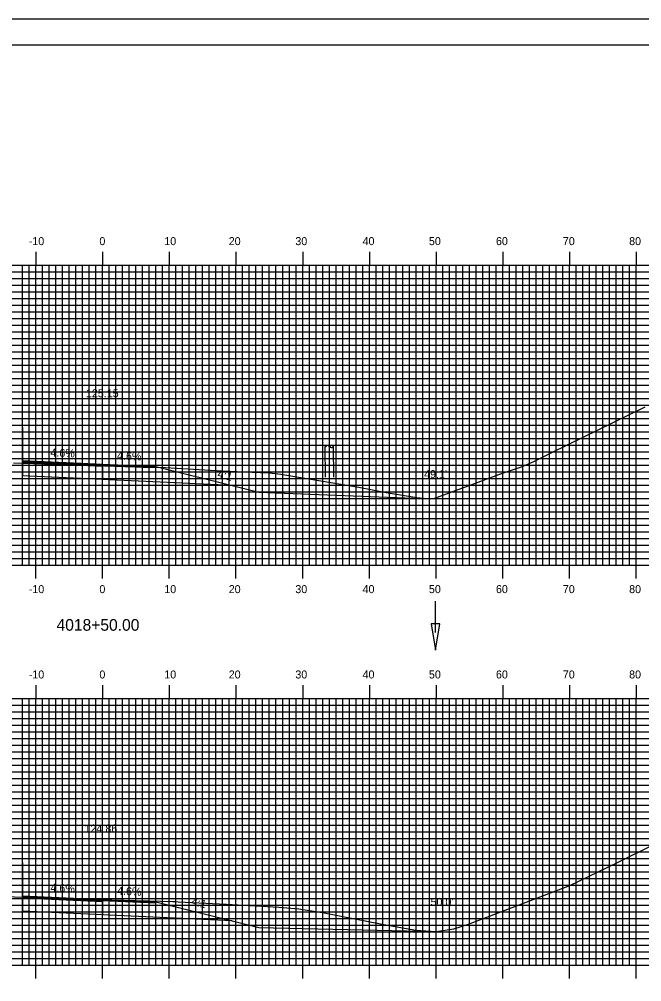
# Model space of a CAD drawing. Extents: x 854508 to 854851, y 364661 to 364881.
# Drawn here: x 854661.3 to 854754.7, y 364736.9 to 364881.3 of the extents above; entities that cross this region are included whole.
import ezdxf

# ---------------------------------------------------------------- set-up
doc = ezdxf.new("R2010")
doc.units = 0
for name, color, linetype in [('ANNOTATION', 7, 'Continuous'), ('BORDER', 7, 'Continuous'), ('D_Drainage_Ditch_Line', 7, 'Continuous'), ('D_Roadway_Centerline_Text', 7, 'Continuous'), ('D_Roadway_Edge_Shoulder', 7, 'Continuous'), ('D_Roadway_Edge_TW', 7, 'Continuous'), ('D_Roadway_Pavement', 7, 'Continuous'), ('D_Roadway_SubGrade', 7, 'Continuous'), ('D_Text_Standard', 7, 'Continuous'), ('H_V ANNOTATION', 7, 'Continuous'), ('M_Roadway_Centerline', 7, 'Continuous'), ('MAJOR', 7, 'Continuous'), ('MINOR', 7, 'Continuous'), ('PLOT BOUNDARY', 7, 'Continuous'), ('S_Roadway_Centerline', 7, 'Continuous'), ('S_Utilities_Pole_StreetLight', 7, 'Continuous')]:
    doc.layers.add(name, color=color, linetype=linetype)

msp = doc.modelspace()

# ---------------------------------------------------------------- linework, layer by layer
at = {"layer": 'ANNOTATION'}
for points in [[(854693.26, 364811.3), (854697.26, 364810.3), (854722.98, 364809.33)], [(854693.25, 364746.01), (854697.25, 364745.01), (854723.85, 364744.4)]]:
    msp.add_lwpolyline(points, dxfattribs=at)
at = {"layer": 'BORDER'}
msp.add_lwpolyline([(854524.23, 364667.37), (854844.23, 364667.37), (854844.23, 364877.37), (854524.23, 364877.37)], close=True, dxfattribs=at)
at = {"layer": 'D_Drainage_Ditch_Line'}
msp.add_line((854723.75, 364789.25), (854723.75, 364793.95), dxfattribs=at)
msp.add_lwpolyline([(854724.4, 364790.56), (854723.09, 364790.56), (854723.75, 364786.63)], close=True, dxfattribs=at)
at = {"layer": 'D_Roadway_Edge_Shoulder'}
for points in [[(854673.83, 364814.52), (854681.83, 364814.15), (854681.83, 364813.99), (854673.83, 364814.36)], [(854673.83, 364749.23), (854681.83, 364748.86), (854681.83, 364748.7), (854673.83, 364749.07)]]:
    msp.add_lwpolyline(points, close=True, dxfattribs=at)
at = {"layer": 'D_Roadway_Edge_TW'}
for points in [[(854661.83, 364815.07), (854673.83, 364814.52), (854673.83, 364814.36), (854661.83, 364814.91)], [(854661.83, 364749.78), (854673.83, 364749.23), (854673.83, 364749.07), (854661.83, 364749.61)]]:
    msp.add_lwpolyline(points, close=True, dxfattribs=at)
at = {"layer": 'D_Roadway_Pavement'}
for points in [[(854661.83, 364814.91), (854673.83, 364814.36), (854673.83, 364814.19), (854661.83, 364814.74)], [(854661.83, 364749.61), (854673.83, 364749.07), (854673.83, 364748.9), (854661.83, 364749.45)]]:
    msp.add_lwpolyline(points, close=True, dxfattribs=at)
for points in [[(854661.83, 364814.91), (854661.83, 364814.74)], [(854673.83, 364814.36), (854673.83, 364814.19)], [(854673.83, 364814.36), (854673.83, 364814.19)], [(854661.83, 364749.61), (854661.83, 364749.45)], [(854673.83, 364749.07), (854673.83, 364748.9)], [(854673.83, 364749.07), (854673.83, 364748.9)]]:
    msp.add_lwpolyline(points, dxfattribs=at)
at = {"layer": 'D_Roadway_SubGrade'}
for p, q in [((854661.83, 364820.03), (854661.83, 364812.74)), ((854661.83, 364754.74), (854661.83, 364747.45))]:
    msp.add_line(p, q, dxfattribs=at)
for points in [[(854661.83, 364814.74), (854673.83, 364814.19), (854673.83, 364812.19), (854661.83, 364812.74)], [(854673.83, 364814.19), (854673.83, 364814.36), (854681.83, 364813.99), (854681.83, 364814.15), (854693.26, 364811.3), (854673.83, 364812.19)], [(854661.83, 364749.45), (854673.83, 364748.9), (854673.83, 364746.9), (854661.83, 364747.45)], [(854673.83, 364748.9), (854673.83, 364749.07), (854681.83, 364748.7), (854681.83, 364748.86), (854693.25, 364746.01), (854673.83, 364746.9)]]:
    msp.add_lwpolyline(points, close=True, dxfattribs=at)
at = {"layer": 'MAJOR'}
for p, q in [((854663.83, 364846.37), (854663.83, 364844.37)), ((854673.83, 364846.37), (854673.83, 364844.37)), ((854683.83, 364846.37), (854683.83, 364844.37)), ((854693.83, 364846.37), (854693.83, 364844.37)), ((854703.83, 364846.37), (854703.83, 364844.37)), ((854713.83, 364846.37), (854713.83, 364844.37)), ((854723.83, 364846.37), (854723.83, 364844.37)), ((854733.83, 364846.37), (854733.83, 364844.37)), ((854743.83, 364846.37), (854743.83, 364844.37)), ((854753.83, 364846.37), (854753.83, 364844.37)), ((854533.83, 364844.37), (854813.83, 364844.37)), ((854533.83, 364844.37), (854813.83, 364844.37)), ((854663.83, 364799.37), (854663.83, 364844.37)), ((854673.83, 364799.37), (854673.83, 364844.37)), ((854683.83, 364799.37), (854683.83, 364844.37)), ((854693.83, 364799.37), (854693.83, 364844.37)), ((854703.83, 364799.37), (854703.83, 364844.37)), ((854713.83, 364799.37), (854713.83, 364844.37)), ((854723.83, 364799.37), (854723.83, 364844.37)), ((854733.83, 364799.37), (854733.83, 364844.37)), ((854743.83, 364799.37), (854743.83, 364844.37)), ((854753.83, 364799.37), (854753.83, 364844.37)), ((854533.83, 364839.37), (854813.83, 364839.37)), ((854533.83, 364834.37), (854813.83, 364834.37)), ((854533.83, 364829.37), (854813.83, 364829.37)), ((854533.83, 364824.37), (854813.83, 364824.37)), ((854533.83, 364819.37), (854813.83, 364819.37)), ((854533.83, 364814.37), (854813.83, 364814.37)), ((854533.83, 364809.37), (854813.83, 364809.37)), ((854533.83, 364804.37), (854813.83, 364804.37)), ((854533.83, 364799.37), (854813.83, 364799.37)), ((854533.83, 364799.37), (854813.83, 364799.37)), ((854663.83, 364797.37), (854663.83, 364799.37)), ((854673.83, 364797.37), (854673.83, 364799.37)), ((854683.83, 364797.37), (854683.83, 364799.37)), ((854693.83, 364797.37), (854693.83, 364799.37)), ((854703.83, 364797.37), (854703.83, 364799.37)), ((854713.83, 364797.37), (854713.83, 364799.37)), ((854723.83, 364797.37), (854723.83, 364799.37)), ((854733.83, 364797.37), (854733.83, 364799.37)), ((854743.83, 364797.37), (854743.83, 364799.37)), ((854753.83, 364797.37), (854753.83, 364799.37)), ((854663.83, 364781.37), (854663.83, 364779.37)), ((854673.83, 364781.37), (854673.83, 364779.37)), ((854683.83, 364781.37), (854683.83, 364779.37)), ((854693.83, 364781.37), (854693.83, 364779.37)), ((854703.83, 364781.37), (854703.83, 364779.37)), ((854713.83, 364781.37), (854713.83, 364779.37)), ((854723.83, 364781.37), (854723.83, 364779.37)), ((854733.83, 364781.37), (854733.83, 364779.37)), ((854743.83, 364781.37), (854743.83, 364779.37)), ((854753.83, 364781.37), (854753.83, 364779.37)), ((854533.83, 364779.37), (854813.83, 364779.37)), ((854533.83, 364779.37), (854813.83, 364779.37)), ((854663.83, 364739.37), (854663.83, 364779.37)), ((854673.83, 364739.37), (854673.83, 364779.37)), ((854683.83, 364739.37), (854683.83, 364779.37)), ((854693.83, 364739.37), (854693.83, 364779.37)), ((854703.83, 364739.37), (854703.83, 364779.37)), ((854713.83, 364739.37), (854713.83, 364779.37)), ((854723.83, 364739.37), (854723.83, 364779.37)), ((854733.83, 364739.37), (854733.83, 364779.37)), ((854743.83, 364739.37), (854743.83, 364779.37)), ((854753.83, 364739.37), (854753.83, 364779.37)), ((854533.83, 364774.37), (854813.83, 364774.37)), ((854533.83, 364769.37), (854813.83, 364769.37)), ((854533.83, 364764.37), (854813.83, 364764.37)), ((854533.83, 364759.37), (854813.83, 364759.37)), ((854533.83, 364754.37), (854813.83, 364754.37)), ((854533.83, 364749.37), (854813.83, 364749.37)), ((854533.83, 364744.37), (854813.83, 364744.37)), ((854533.83, 364739.37), (854813.83, 364739.37)), ((854533.83, 364739.37), (854813.83, 364739.37)), ((854663.83, 364737.37), (854663.83, 364739.37)), ((854673.83, 364737.37), (854673.83, 364739.37)), ((854683.83, 364737.37), (854683.83, 364739.37)), ((854693.83, 364737.37), (854693.83, 364739.37)), ((854703.83, 364737.37), (854703.83, 364739.37)), ((854713.83, 364737.37), (854713.83, 364739.37)), ((854723.83, 364737.37), (854723.83, 364739.37)), ((854733.83, 364737.37), (854733.83, 364739.37)), ((854743.83, 364737.37), (854743.83, 364739.37)), ((854753.83, 364737.37), (854753.83, 364739.37))]:
    msp.add_line(p, q, dxfattribs=at)
at = {"layer": 'MINOR'}
for p, q in [((854661.83, 364799.37), (854661.83, 364844.37)), ((854662.83, 364799.37), (854662.83, 364844.37)), ((854664.83, 364799.37), (854664.83, 364844.37)), ((854665.83, 364799.37), (854665.83, 364844.37)), ((854666.83, 364799.37), (854666.83, 364844.37)), ((854667.83, 364799.37), (854667.83, 364844.37)), ((854668.83, 364799.37), (854668.83, 364844.37)), ((854669.83, 364799.37), (854669.83, 364844.37)), ((854670.83, 364799.37), (854670.83, 364844.37)), ((854671.83, 364799.37), (854671.83, 364844.37)), ((854672.83, 364799.37), (854672.83, 364844.37)), ((854674.83, 364799.37), (854674.83, 364844.37)), ((854675.83, 364799.37), (854675.83, 364844.37)), ((854676.83, 364799.37), (854676.83, 364844.37)), ((854677.83, 364799.37), (854677.83, 364844.37)), ((854678.83, 364799.37), (854678.83, 364844.37)), ((854679.83, 364799.37), (854679.83, 364844.37)), ((854680.83, 364799.37), (854680.83, 364844.37)), ((854681.83, 364799.37), (854681.83, 364844.37)), ((854682.83, 364799.37), (854682.83, 364844.37)), ((854684.83, 364799.37), (854684.83, 364844.37)), ((854685.83, 364799.37), (854685.83, 364844.37)), ((854686.83, 364799.37), (854686.83, 364844.37)), ((854687.83, 364799.37), (854687.83, 364844.37)), ((854688.83, 364799.37), (854688.83, 364844.37)), ((854689.83, 364799.37), (854689.83, 364844.37)), ((854690.83, 364799.37), (854690.83, 364844.37)), ((854691.83, 364799.37), (854691.83, 364844.37)), ((854692.83, 364799.37), (854692.83, 364844.37)), ((854694.83, 364799.37), (854694.83, 364844.37)), ((854695.83, 364799.37), (854695.83, 364844.37)), ((854696.83, 364799.37), (854696.83, 364844.37)), ((854697.83, 364799.37), (854697.83, 364844.37)), ((854698.83, 364799.37), (854698.83, 364844.37)), ((854699.83, 364799.37), (854699.83, 364844.37)), ((854700.83, 364799.37), (854700.83, 364844.37)), ((854701.83, 364799.37), (854701.83, 364844.37)), ((854702.83, 364799.37), (854702.83, 364844.37)), ((854704.83, 364799.37), (854704.83, 364844.37)), ((854705.83, 364799.37), (854705.83, 364844.37)), ((854706.83, 364799.37), (854706.83, 364844.37)), ((854707.83, 364799.37), (854707.83, 364844.37)), ((854708.83, 364799.37), (854708.83, 364844.37)), ((854709.83, 364799.37), (854709.83, 364844.37)), ((854710.83, 364799.37), (854710.83, 364844.37)), ((854711.83, 364799.37), (854711.83, 364844.37)), ((854712.83, 364799.37), (854712.83, 364844.37)), ((854714.83, 364799.37), (854714.83, 364844.37)), ((854715.83, 364799.37), (854715.83, 364844.37)), ((854716.83, 364799.37), (854716.83, 364844.37)), ((854717.83, 364799.37), (854717.83, 364844.37)), ((854718.83, 364799.37), (854718.83, 364844.37)), ((854719.83, 364799.37), (854719.83, 364844.37)), ((854720.83, 364799.37), (854720.83, 364844.37)), ((854721.83, 364799.37), (854721.83, 364844.37)), ((854722.83, 364799.37), (854722.83, 364844.37)), ((854724.83, 364799.37), (854724.83, 364844.37)), ((854725.83, 364799.37), (854725.83, 364844.37)), ((854726.83, 364799.37), (854726.83, 364844.37)), ((854727.83, 364799.37), (854727.83, 364844.37)), ((854728.83, 364799.37), (854728.83, 364844.37)), ((854729.83, 364799.37), (854729.83, 364844.37)), ((854730.83, 364799.37), (854730.83, 364844.37)), ((854731.83, 364799.37), (854731.83, 364844.37)), ((854732.83, 364799.37), (854732.83, 364844.37)), ((854734.83, 364799.37), (854734.83, 364844.37)), ((854735.83, 364799.37), (854735.83, 364844.37)), ((854736.83, 364799.37), (854736.83, 364844.37)), ((854737.83, 364799.37), (854737.83, 364844.37)), ((854738.83, 364799.37), (854738.83, 364844.37)), ((854739.83, 364799.37), (854739.83, 364844.37)), ((854740.83, 364799.37), (854740.83, 364844.37)), ((854741.83, 364799.37), (854741.83, 364844.37)), ((854742.83, 364799.37), (854742.83, 364844.37)), ((854744.83, 364799.37), (854744.83, 364844.37)), ((854745.83, 364799.37), (854745.83, 364844.37)), ((854746.83, 364799.37), (854746.83, 364844.37)), ((854747.83, 364799.37), (854747.83, 364844.37)), ((854748.83, 364799.37), (854748.83, 364844.37)), ((854749.83, 364799.37), (854749.83, 364844.37)), ((854750.83, 364799.37), (854750.83, 364844.37)), ((854751.83, 364799.37), (854751.83, 364844.37)), ((854752.83, 364799.37), (854752.83, 364844.37)), ((854533.83, 364843.37), (854813.83, 364843.37)), ((854533.83, 364842.37), (854813.83, 364842.37)), ((854533.83, 364841.37), (854813.83, 364841.37)), ((854533.83, 364840.37), (854813.83, 364840.37)), ((854533.83, 364838.37), (854813.83, 364838.37)), ((854533.83, 364837.37), (854813.83, 364837.37)), ((854533.83, 364836.37), (854813.83, 364836.37)), ((854533.83, 364835.37), (854813.83, 364835.37)), ((854533.83, 364833.37), (854813.83, 364833.37)), ((854533.83, 364832.37), (854813.83, 364832.37)), ((854533.83, 364831.37), (854813.83, 364831.37)), ((854533.83, 364830.37), (854813.83, 364830.37)), ((854533.83, 364828.37), (854813.83, 364828.37)), ((854533.83, 364827.37), (854813.83, 364827.37)), ((854533.83, 364826.37), (854813.83, 364826.37)), ((854533.83, 364825.37), (854813.83, 364825.37)), ((854533.83, 364823.37), (854813.83, 364823.37)), ((854533.83, 364822.37), (854813.83, 364822.37)), ((854533.83, 364821.37), (854813.83, 364821.37)), ((854533.83, 364820.37), (854813.83, 364820.37)), ((854533.83, 364818.37), (854813.83, 364818.37)), ((854533.83, 364817.37), (854813.83, 364817.37)), ((854533.83, 364816.37), (854813.83, 364816.37)), ((854533.83, 364815.37), (854813.83, 364815.37)), ((854533.83, 364813.37), (854813.83, 364813.37)), ((854533.83, 364812.37), (854813.83, 364812.37)), ((854533.83, 364811.37), (854813.83, 364811.37)), ((854533.83, 364810.37), (854813.83, 364810.37)), ((854533.83, 364808.37), (854813.83, 364808.37)), ((854533.83, 364807.37), (854813.83, 364807.37)), ((854533.83, 364806.37), (854813.83, 364806.37)), ((854533.83, 364805.37), (854813.83, 364805.37)), ((854533.83, 364803.37), (854813.83, 364803.37)), ((854533.83, 364802.37), (854813.83, 364802.37)), ((854533.83, 364801.37), (854813.83, 364801.37)), ((854533.83, 364800.37), (854813.83, 364800.37)), ((854661.83, 364739.37), (854661.83, 364779.37)), ((854662.83, 364739.37), (854662.83, 364779.37)), ((854664.83, 364739.37), (854664.83, 364779.37)), ((854665.83, 364739.37), (854665.83, 364779.37)), ((854666.83, 364739.37), (854666.83, 364779.37)), ((854667.83, 364739.37), (854667.83, 364779.37)), ((854668.83, 364739.37), (854668.83, 364779.37)), ((854669.83, 364739.37), (854669.83, 364779.37)), ((854670.83, 364739.37), (854670.83, 364779.37)), ((854671.83, 364739.37), (854671.83, 364779.37)), ((854672.83, 364739.37), (854672.83, 364779.37)), ((854674.83, 364739.37), (854674.83, 364779.37)), ((854675.83, 364739.37), (854675.83, 364779.37)), ((854676.83, 364739.37), (854676.83, 364779.37)), ((854677.83, 364739.37), (854677.83, 364779.37)), ((854678.83, 364739.37), (854678.83, 364779.37)), ((854679.83, 364739.37), (854679.83, 364779.37)), ((854680.83, 364739.37), (854680.83, 364779.37)), ((854681.83, 364739.37), (854681.83, 364779.37)), ((854682.83, 364739.37), (854682.83, 364779.37)), ((854684.83, 364739.37), (854684.83, 364779.37)), ((854685.83, 364739.37), (854685.83, 364779.37)), ((854686.83, 364739.37), (854686.83, 364779.37)), ((854687.83, 364739.37), (854687.83, 364779.37)), ((854688.83, 364739.37), (854688.83, 364779.37)), ((854689.83, 364739.37), (854689.83, 364779.37)), ((854690.83, 364739.37), (854690.83, 364779.37)), ((854691.83, 364739.37), (854691.83, 364779.37)), ((854692.83, 364739.37), (854692.83, 364779.37)), ((854694.83, 364739.37), (854694.83, 364779.37)), ((854695.83, 364739.37), (854695.83, 364779.37)), ((854696.83, 364739.37), (854696.83, 364779.37)), ((854697.83, 364739.37), (854697.83, 364779.37)), ((854698.83, 364739.37), (854698.83, 364779.37)), ((854699.83, 364739.37), (854699.83, 364779.37)), ((854700.83, 364739.37), (854700.83, 364779.37)), ((854701.83, 364739.37), (854701.83, 364779.37)), ((854702.83, 364739.37), (854702.83, 364779.37)), ((854704.83, 364739.37), (854704.83, 364779.37)), ((854705.83, 364739.37), (854705.83, 364779.37)), ((854706.83, 364739.37), (854706.83, 364779.37)), ((854707.83, 364739.37), (854707.83, 364779.37)), ((854708.83, 364739.37), (854708.83, 364779.37)), ((854709.83, 364739.37), (854709.83, 364779.37)), ((854710.83, 364739.37), (854710.83, 364779.37)), ((854711.83, 364739.37), (854711.83, 364779.37)), ((854712.83, 364739.37), (854712.83, 364779.37)), ((854714.83, 364739.37), (854714.83, 364779.37)), ((854715.83, 364739.37), (854715.83, 364779.37)), ((854716.83, 364739.37), (854716.83, 364779.37)), ((854717.83, 364739.37), (854717.83, 364779.37)), ((854718.83, 364739.37), (854718.83, 364779.37)), ((854719.83, 364739.37), (854719.83, 364779.37)), ((854720.83, 364739.37), (854720.83, 364779.37)), ((854721.83, 364739.37), (854721.83, 364779.37)), ((854722.83, 364739.37), (854722.83, 364779.37)), ((854724.83, 364739.37), (854724.83, 364779.37)), ((854725.83, 364739.37), (854725.83, 364779.37)), ((854726.83, 364739.37), (854726.83, 364779.37)), ((854727.83, 364739.37), (854727.83, 364779.37)), ((854728.83, 364739.37), (854728.83, 364779.37)), ((854729.83, 364739.37), (854729.83, 364779.37)), ((854730.83, 364739.37), (854730.83, 364779.37)), ((854731.83, 364739.37), (854731.83, 364779.37)), ((854732.83, 364739.37), (854732.83, 364779.37)), ((854734.83, 364739.37), (854734.83, 364779.37)), ((854735.83, 364739.37), (854735.83, 364779.37)), ((854736.83, 364739.37), (854736.83, 364779.37)), ((854737.83, 364739.37), (854737.83, 364779.37)), ((854738.83, 364739.37), (854738.83, 364779.37)), ((854739.83, 364739.37), (854739.83, 364779.37)), ((854740.83, 364739.37), (854740.83, 364779.37)), ((854741.83, 364739.37), (854741.83, 364779.37)), ((854742.83, 364739.37), (854742.83, 364779.37)), ((854744.83, 364739.37), (854744.83, 364779.37)), ((854745.83, 364739.37), (854745.83, 364779.37)), ((854746.83, 364739.37), (854746.83, 364779.37)), ((854747.83, 364739.37), (854747.83, 364779.37)), ((854748.83, 364739.37), (854748.83, 364779.37)), ((854749.83, 364739.37), (854749.83, 364779.37)), ((854750.83, 364739.37), (854750.83, 364779.37)), ((854751.83, 364739.37), (854751.83, 364779.37)), ((854752.83, 364739.37), (854752.83, 364779.37)), ((854533.83, 364778.37), (854813.83, 364778.37)), ((854533.83, 364777.37), (854813.83, 364777.37)), ((854533.83, 364776.37), (854813.83, 364776.37)), ((854533.83, 364775.37), (854813.83, 364775.37)), ((854533.83, 364773.37), (854813.83, 364773.37)), ((854533.83, 364772.37), (854813.83, 364772.37)), ((854533.83, 364771.37), (854813.83, 364771.37)), ((854533.83, 364770.37), (854813.83, 364770.37)), ((854533.83, 364768.37), (854813.83, 364768.37)), ((854533.83, 364767.37), (854813.83, 364767.37)), ((854533.83, 364766.37), (854813.83, 364766.37)), ((854533.83, 364765.37), (854813.83, 364765.37)), ((854533.83, 364763.37), (854813.83, 364763.37)), ((854533.83, 364762.37), (854813.83, 364762.37)), ((854533.83, 364761.37), (854813.83, 364761.37)), ((854533.83, 364760.37), (854813.83, 364760.37)), ((854533.83, 364758.37), (854813.83, 364758.37)), ((854533.83, 364757.37), (854813.83, 364757.37)), ((854533.83, 364756.37), (854813.83, 364756.37)), ((854533.83, 364755.37), (854813.83, 364755.37)), ((854533.83, 364753.37), (854813.83, 364753.37)), ((854533.83, 364752.37), (854813.83, 364752.37)), ((854533.83, 364751.37), (854813.83, 364751.37)), ((854533.83, 364750.37), (854813.83, 364750.37)), ((854533.83, 364748.37), (854813.83, 364748.37)), ((854533.83, 364747.37), (854813.83, 364747.37)), ((854533.83, 364746.37), (854813.83, 364746.37)), ((854533.83, 364745.37), (854813.83, 364745.37)), ((854533.83, 364743.37), (854813.83, 364743.37)), ((854533.83, 364742.37), (854813.83, 364742.37)), ((854533.83, 364741.37), (854813.83, 364741.37)), ((854533.83, 364740.37), (854813.83, 364740.37))]:
    msp.add_line(p, q, dxfattribs=at)
at = {"layer": 'PLOT BOUNDARY'}
msp.add_lwpolyline([(854508.05, 364661.25), (854848.05, 364661.25), (854848.05, 364881.25), (854508.05, 364881.25)], close=True, dxfattribs=at)
at = {"layer": 'S_Roadway_Centerline'}
for points in [[(854660.46, 364814.7), (854678.65, 364814.12), (854679.69, 364814.09), (854679.93, 364814.08), (854683.28, 364814.01), (854690.03, 364813.62), (854691.85, 364813.49), (854696.23, 364813.3), (854698.81, 364813.19), (854700.55, 364813.01), (854712.26, 364811.06), (854716.35, 364810.26), (854720.96, 364809.53), (854722.98, 364809.33), (854723.51, 364809.37), (854733.79, 364813.17), (854736.66, 364814.1), (854738.47, 364814.92), (854741.19, 364816.27), (854755.18, 364823.11)], [(854655.84, 364749.75), (854666.91, 364749.4), (854667.52, 364749.38), (854671.56, 364749.27), (854684.34, 364748.9), (854684.69, 364748.89), (854684.71, 364748.89), (854685.18, 364748.86), (854691.37, 364748.57), (854692.4, 364748.51), (854700.25, 364748.05), (854703.25, 364747.79), (854707.03, 364747.2), (854715.98, 364745.45), (854720.81, 364744.59), (854723.85, 364744.4), (854726.51, 364744.81), (854728.71, 364745.5), (854743.91, 364751.33), (854751.06, 364754.74), (854756.47, 364757.44)]]:
    msp.add_lwpolyline(points, dxfattribs=at)
at = {"layer": 'S_Utilities_Pole_StreetLight'}
for p, q in [((854707.23, 364812.54), (854707.22, 364817.16)), ((854707.23, 364817.16), (854707.38, 364817.27)), ((854707.69, 364817.27), (854707.85, 364817.16)), ((854708.01, 364817.27), (854707.85, 364817.16)), ((854707.85, 364817.16), (854708.01, 364817.05)), ((854708.48, 364817.16), (854708.32, 364817.27)), ((854708.32, 364817.05), (854708.48, 364817.16)), ((854708.48, 364812.54), (854708.47, 364817.16))]:
    msp.add_line(p, q, dxfattribs=at)
for centre, start, end in [((854707.54, 364817.05), 90, 125.2644), ((854707.54, 364817.05), 54.7356, 90), ((854708.16, 364817.05), 90, 125.2644), ((854708.16, 364817.27), 234.7356, 270), ((854708.16, 364817.05), 54.7356, 90), ((854708.16, 364817.27), 270, 305.2644)]:
    msp.add_arc(centre, 0.271, start, end, dxfattribs=at)

# ---------------------------------------------------------------- texts
at = {"layer": 'ANNOTATION'}
for s, rotation, p in [('4.6%', 357.3663, (854665.98, 364815.69)), ('4.6%', 357.3663, (854675.98, 364815.23)), ('4:1', 345.9638, (854690.96, 364812.54)), ('4.6%', 357.3663, (854665.98, 364750.4)), ('4.6%', 357.3663, (854675.98, 364749.94)), ('4:1', 345.9638, (854687.05, 364748.42))]:
    msp.add_text(s, height=1.2, rotation=rotation, dxfattribs=at).set_placement(p)
at = {"layer": 'D_Roadway_Centerline_Text'}
for s, p in [('125.15', (854671.33, 364824.55)), ('124.86', (854671.12, 364759.26))]:
    msp.add_text(s, height=1.2, dxfattribs=at).set_placement(p)
at = {"layer": 'D_Text_Standard'}
for s, p in [("49.1'", (854722.04, 364812.42)), ("50.0'", (854723, 364748.25))]:
    msp.add_text(s, height=1.2, dxfattribs=at).set_placement(p)
at = {"layer": 'H_V ANNOTATION'}
for s, height, p in [('-10', 1.2, (854662.76, 364847.37)), ('0', 1.2, (854673.35, 364847.37)), ('10', 1.2, (854683.08, 364847.37)), ('20', 1.2, (854692.74, 364847.37)), ('30', 1.2, (854702.73, 364847.37)), ('40', 1.2, (854712.81, 364847.37)), ('50', 1.2, (854722.76, 364847.37)), ('60', 1.2, (854732.81, 364847.37)), ('70', 1.2, (854742.84, 364847.37)), ('80', 1.2, (854752.78, 364847.37)), ('-10', 1.2, (854662.76, 364795.17)), ('0', 1.2, (854673.35, 364795.17)), ('10', 1.2, (854683.08, 364795.17)), ('20', 1.2, (854692.74, 364795.17)), ('30', 1.2, (854702.73, 364795.17)), ('40', 1.2, (854712.81, 364795.17)), ('50', 1.2, (854722.76, 364795.17)), ('60', 1.2, (854732.81, 364795.17)), ('70', 1.2, (854742.84, 364795.17)), ('80', 1.2, (854752.78, 364795.17)), ('4018+50.00', 1.75, (854666.92, 364789.53)), ('-10', 1.2, (854662.76, 364782.37)), ('0', 1.2, (854673.35, 364782.37)), ('10', 1.2, (854683.08, 364782.37)), ('20', 1.2, (854692.74, 364782.37)), ('30', 1.2, (854702.73, 364782.37)), ('40', 1.2, (854712.81, 364782.37)), ('50', 1.2, (854722.76, 364782.37)), ('60', 1.2, (854732.81, 364782.37)), ('70', 1.2, (854742.84, 364782.37)), ('80', 1.2, (854752.78, 364782.37))]:
    msp.add_text(s, height=height, dxfattribs=at).set_placement(p)
at = {"layer": 'M_Roadway_Centerline'}
for s, p in [('C', (854683.27, 364814.01)), ('L', (854683.28, 364814)), ('C', (854684.69, 364748.89)), ('L', (854684.69, 364748.88))]:
    msp.add_text(s, height=0.0146, dxfattribs=at).set_placement(p)

doc.saveas('drawing.dxf')
